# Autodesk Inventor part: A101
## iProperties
Author: Administrator
Revision Number: A
Created: 2001-01
Part Number: A101
Project: PLANE ASSEMBLY
Description: BLADE
Document SubType Name: Modeling
Designer: E. MOSS
Control State: 0
Master: False
Checked Out: False
PropertySet Name: Design Tracking Control
Shininess: 0.0
PropertySet Name: _Private Model Information
Density: 0.0
Volumn: 0.0
Area: 0.0
PropertySet Name: Model Information
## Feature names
1. Extrusion1
2. Extrusion2
3. Chamfer1
